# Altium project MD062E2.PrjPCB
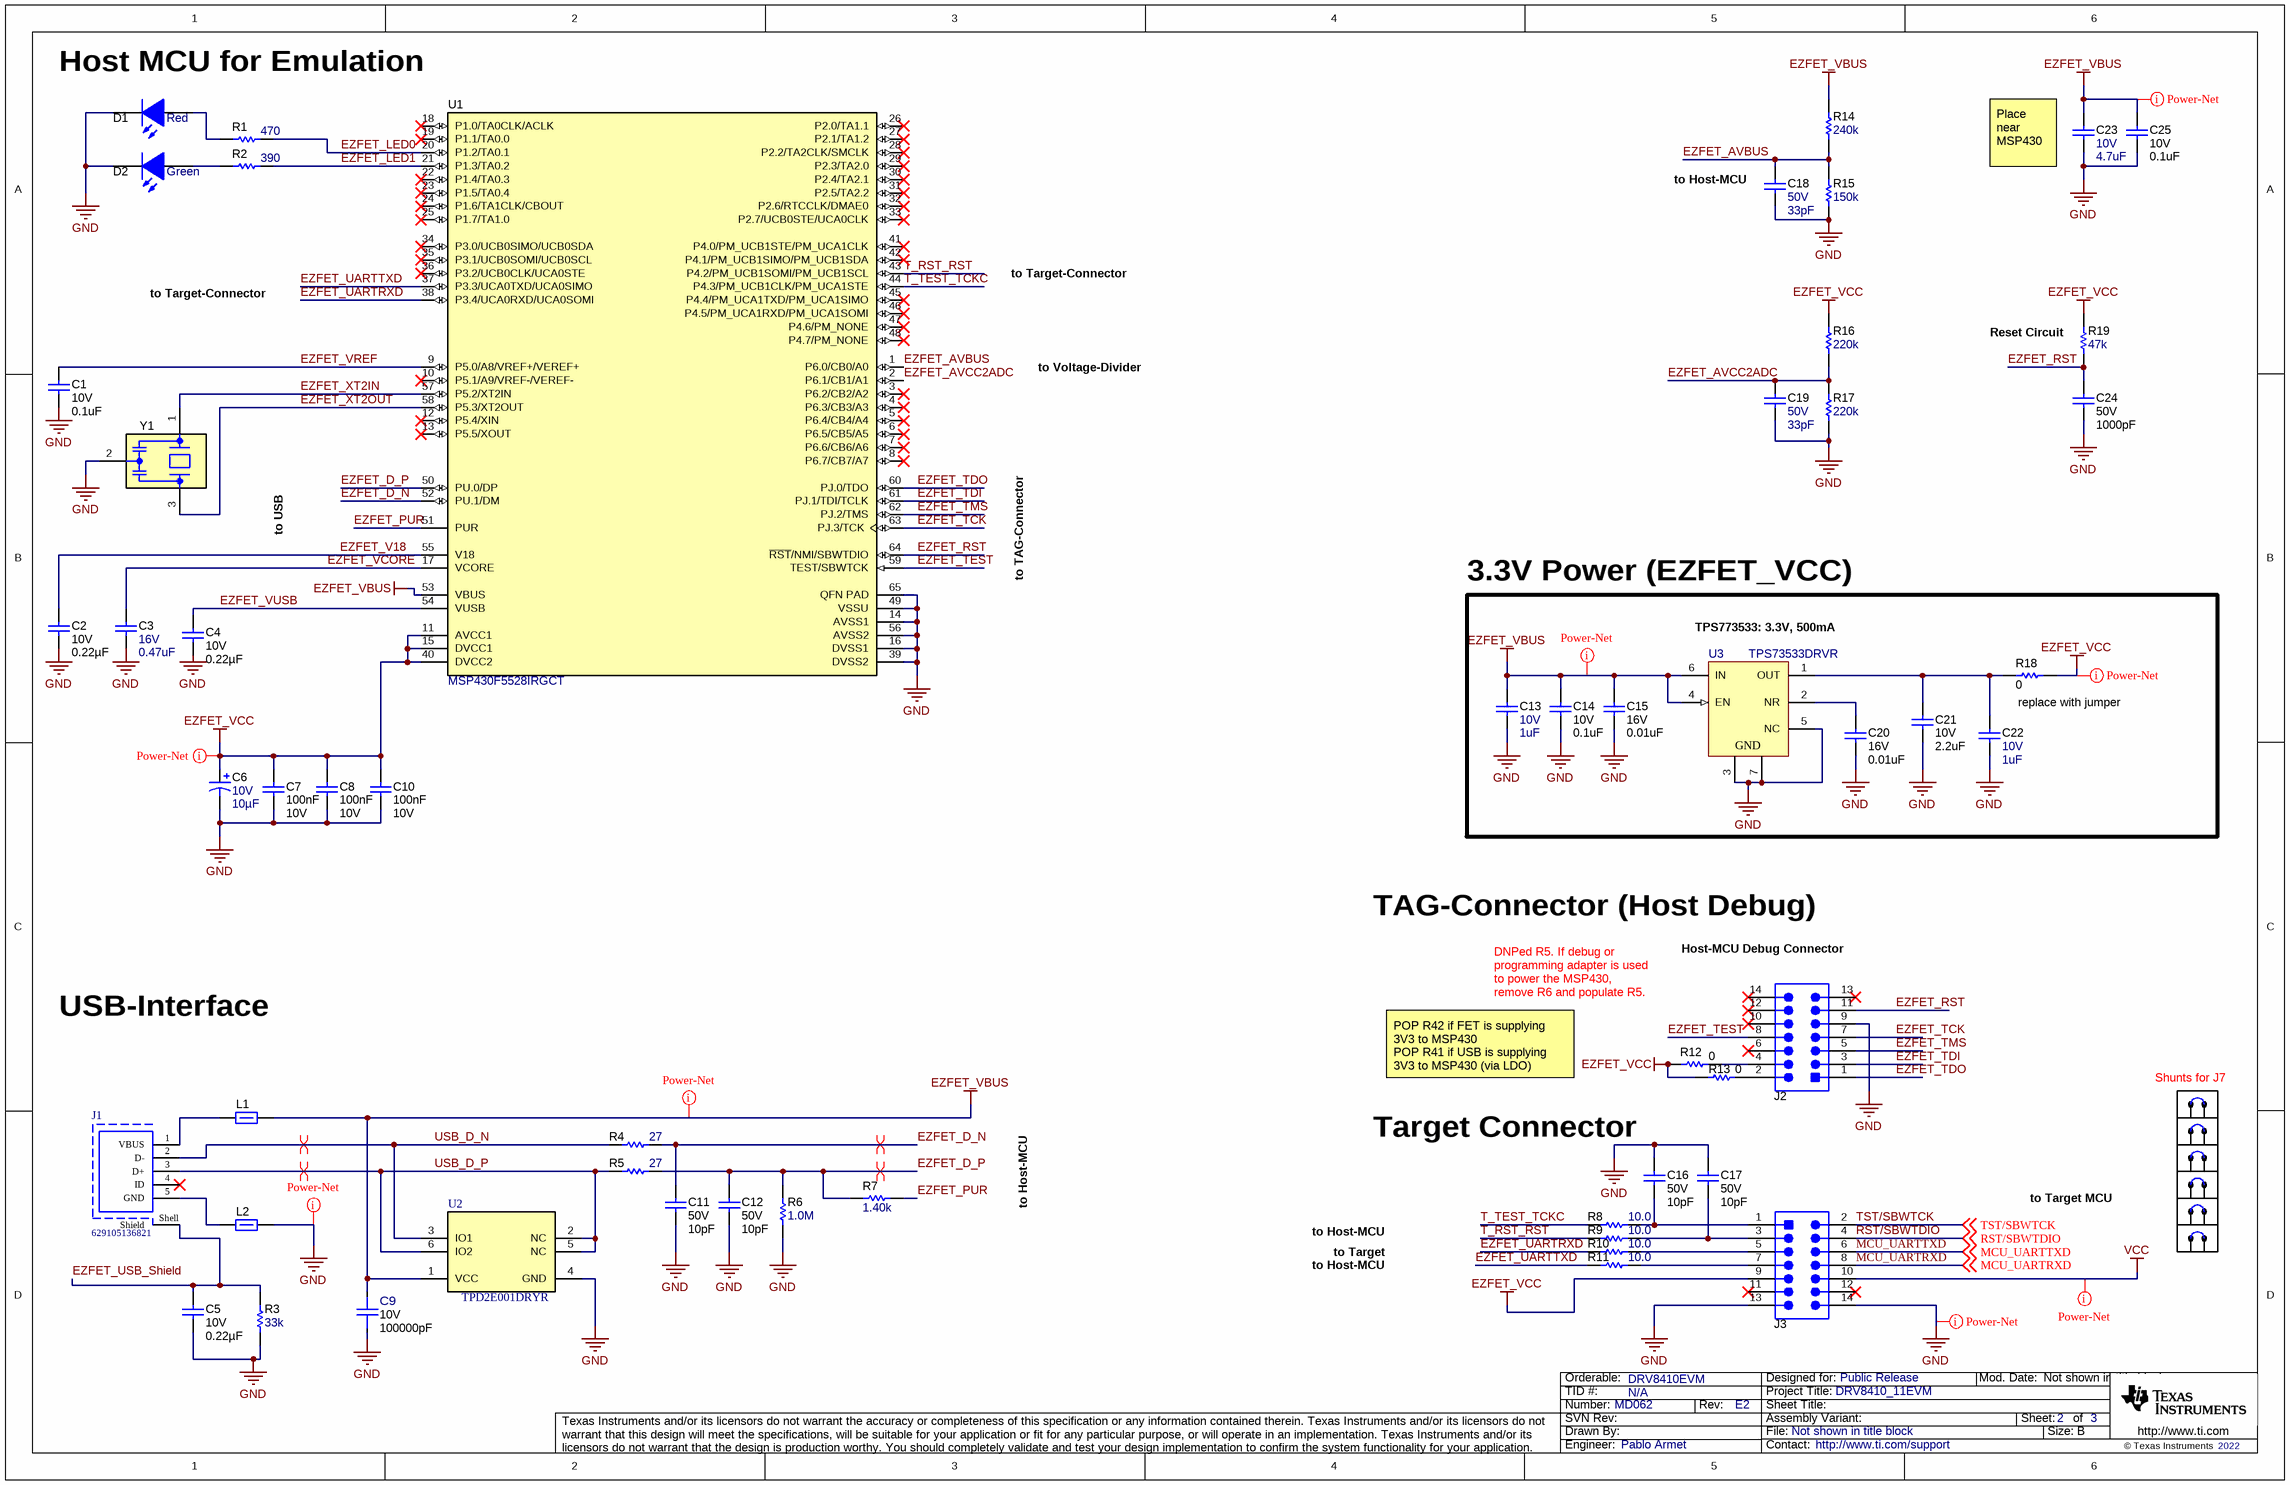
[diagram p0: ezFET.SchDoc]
CopyrightYear: 2022; EVM_Orderable: DRV8410EVM; PCB_Layout: Pablo Armet; PCB_Rev: E2; PRJ_Customer: Public Release; PRJ_Engineer: Pablo Armet; PRJ_Number: MD062; PRJ_Title: DRV8410_11EVM; SCH_Rev: E2; TechSupport: http://www.ti.com/support; TID: N/A
3 sheets, 173 parts. Net scope: global (net labels, ports and power ports of the same name join across sheets).
Board file: MD062E2_PCB.PcbDoc
Sheets:
  ezFET.SchDoc
  MD062E2_Hardware.SchDoc
  MD062E2_Sch.SchDoc

## Sheet ezFET.SchDoc
size 431 x 279 mm; Date: Not shown in title block; ApprovedBy: Not shown in title block; CheckedBy: Not shown in title block; Author: Not shown in title block; CompanyName: Not shown in title block; Engineer: Not shown in title block; Organization: Not shown in title block; Address1: Not shown in title block; Address2: Not shown in title block; Address3: Not shown in title block; Address4: Not shown in title block; DocumentNumber: 2; Revision: Use project parameter SCH_Rev; SheetNumber: 2; SheetTotal: 3; PageSetup: Record=PageOptions¦CenterHorizontal=True¦CenterVertical=True¦PrintScale=1.00¦XCorrection=1.00¦YCorrection=1.00¦PrintKind=0¦BorderSize=5000000¦LeftOffset=0¦BottomOffset=0¦Orientation=2¦PaperLength=1000¦PaperWidth=1000¦Scale=100¦PaperSource=15¦PrintQuality=600¦MediaType=1¦DitherType=10¦PaperKind=Letter¦PrintScaleMode=1

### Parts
C1  VDC_V: 10V  ValueDisplayed: 0.1uF  [0402L]  (hidden comment: 885012105010)
C2  VDC_V: 10V  ValueDisplayed: 0.22µF  [0402L]  (hidden comment: 885012105011)
C3  VDC_V: 16V  ValueDisplayed: 0.47uF  [0402L]  (hidden comment: GRM155R61C474KE01)
C4  VDC_V: 10V  ValueDisplayed: 0.22µF  [0402L]  (hidden comment: 885012105011)
C5  VDC_V: 10V  ValueDisplayed: 0.22µF  [0402S]  (hidden comment: 885012105011)
C6  VDC_V: 10V  ValueDisplayed: 10µF  [3216-18]  (hidden comment: T520A106M010ATE080)
C7  Cap_F: 100nF  VDC_V: 10V  [0603L]  (hidden comment: 885012206020)
C8  Cap_F: 100nF  VDC_V: 10V  [0603L]  (hidden comment: 885012206020)
C9  VDC_V: 10V  ValueDisplayed: 100000pF  [FP-885012205018_0402-MFG]  (hidden comment: 885012205018)
C10  Cap_F: 100nF  VDC_V: 10V  [0603L]  (hidden comment: 885012206020)
C11  VDC_V: 50V  ValueDisplayed: 10pF  [0402L]  (hidden comment: 885012005055)
C12  VDC_V: 50V  ValueDisplayed: 10pF  [0402L]  (hidden comment: 885012005055)
C13  VDC_V: 10V  ValueDisplayed: 1uF  [0402S]  (hidden comment: 885012105012)
C14  VDC_V: 10V  ValueDisplayed: 0.1uF  [0402S]  (hidden comment: 885012105010)
C15  VDC_V: 16V  ValueDisplayed: 0.01uF  [0402S]  (hidden comment: 885012205031)
C16  VDC_V: 50V  ValueDisplayed: 10pF  [0402L]  (hidden comment: 885012005055)
C17  VDC_V: 50V  ValueDisplayed: 10pF  [0402L]  (hidden comment: 885012005055)
C18  VDC_V: 50V  ValueDisplayed: 33pF  [0402L]  (hidden comment: C1005C0G1H330J050BA)
C19  VDC_V: 50V  ValueDisplayed: 33pF  [0402L]  (hidden comment: C1005C0G1H330J050BA)
C20  VDC_V: 16V  ValueDisplayed: 0.01uF  [0402S]  (hidden comment: 885012205031)
C21  VDC_V: 10V  ValueDisplayed: 2.2uF  [0402S]  (hidden comment: 885012105013)
C22  VDC_V: 10V  ValueDisplayed: 1uF  [0402S]  (hidden comment: 885012105012)
C23  VDC_V: 10V  ValueDisplayed: 4.7uF  [0402S]  (hidden comment: C1005X5R1A475M050BC)
C24  VDC_V: 50V  ValueDisplayed: 1000pF  [0402L]  (hidden comment: 885012205061)
C25  VDC_V: 10V  ValueDisplayed: 0.1uF  [0402S]  (hidden comment: GRM155R61A104KA01D)
D1  value Red  [WL-SMCW_RED]  (hidden comment: 150060RS75000)
D2  value Green  [WL-SMCW_GREEN]  (hidden comment: CMP-0002894-2)
J1  629105136821  [629105136821]
J2  61301421121  [Wurth_61301421121]  (value not drawn)
J3  61301421121  [Wurth_61301421121]  (value not drawn)
L1  742792621  [0603L]  (value not drawn)
L2  742792621  [0603L]  (value not drawn)
R1  ValueDisplayed: 470  [0402L]  (hidden comment: CRCW0402470RJNED)
R2  ValueDisplayed: 390  [0402L]  (hidden comment: CRCW0402390RJNED)
R3  ValueDisplayed: 33k  [0402S]  (hidden comment: CRCW040233K0JNED)
R4  ValueDisplayed: 27  [0402L]  (hidden comment: CRCW040227R0JNED)
R5  ValueDisplayed: 27  [0402L]  (hidden comment: CRCW040227R0JNED)
R6  ValueDisplayed: 1.0M  [0402L]  (hidden comment: CRCW04021M00JNED)
R7  ValueDisplayed: 1.40k  [0402L]  (hidden comment: CRCW04021K40FKED)
R8  ValueDisplayed: 10.0  [0402S]  (hidden comment: CRCW040210R0FKED)
R9  ValueDisplayed: 10.0  [0402S]  (hidden comment: CRCW040210R0FKED)
R10  ValueDisplayed: 10.0  [0402S]  (hidden comment: CRCW040210R0FKED)
R11  ValueDisplayed: 10.0  [0402S]  (hidden comment: CRCW040210R0FKED)
R12  value 0  [0402L]  (hidden comment: ERJ-2GE0R00X)
R13  value 0  [0402L]  (hidden comment: ERJ-2GE0R00X)
R14  ValueDisplayed: 240k  [0402L]  (hidden comment: CRCW0402240KFKED)
R15  ValueDisplayed: 150k  [0402L]  (hidden comment: CRCW0402150KFKED)
R16  ValueDisplayed: 220k  [0402L]  (hidden comment: RC0402FR-07220KL)
R17  ValueDisplayed: 220k  [0402L]  (hidden comment: RC0402FR-07220KL)
R18  ValueDisplayed: 0  [0402S]  (hidden comment: CRCW04020000Z0EDHP)
R19  ValueDisplayed: 47k  [0402L]  (hidden comment: CRCW040247K0JNED)
SH-J1  60900213421  [Wurth_60900213421]  (value not drawn)
SH-J2  60900213421  [Wurth_60900213421]  (value not drawn)
SH-J3  60900213421  [Wurth_60900213421]  (value not drawn)
SH-J4  60900213421  [Wurth_60900213421]  (value not drawn)
SH-J5  60900213421  [Wurth_60900213421]  (value not drawn)
SH-J6  60900213421  [Wurth_60900213421]  (value not drawn)
U1  PartNumber: MSP430F5528IRGCT  [RGC0064B]  (hidden comment: CMP-0039269-4)
U2  TPD2E001DRYR  [DRY0006A]
U3  TPS73533DRVR  [DRV0006A]
Y1  CSTNR4M00GH5L000R0  [MuRata_CSTNR]  (value not drawn)

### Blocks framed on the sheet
3.3V Power (EZFET_VCC): C13-C15 C20-C22 R18 U3

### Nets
EZFET_VBUS: C9.2 C13.1 C14.1 C15.1 C23.1 C25.1 L1.2 R14.2 U1.53(VBUS) U2.1(VCC) U3.4(EN) U3.6(IN)
EZFET_VCC: C6.1(+) C7.1 C8.1 C10.1 J3.9 R12.1 R13.1 R16.2 R18.2 R19.2 U1.11(AVCC1) U1.15(DVCC1) U1.40(DVCC2)
GND: C1.2 C2.2 C3.2 C4.2 C5.2 C6.2(-) C7.2 C8.2 C9.1 C10.2 C11.2 C12.2 C13.2 C14.2 C15.2 C16.1 C17.1 C18.2 C19.2 C20.2 C21.2 C22.2 C23.2 C24.2 C25.2 D1.1(K) D2.1(K) J2.9 J3.13 J3.14 L2.2 R3.1 R6.1 R15.1 R17.1 U1.14(AVSS1) U1.16(DVSS1) U1.39(DVSS2) U1.49(VSSU) U1.56(AVSS2) U1.65(QFN_PAD) U2.4(GND) U3.3(GND) U3.5(NC) U3.7(GND) Y1.2(GND)
VCC: J3.10
EZFET_AVBUS: C18.1 R14.1 R15.2 U1.1(P6.0/CB0/A0)
EZFET_AVCC2ADC: C19.1 R16.1 R17.2 U1.2(P6.1/CB1/A1)
EZFET_D_N: C11.1 R4.2 U1.52(PU.1/DM)
EZFET_D_P: C12.1 R5.2 R6.2 R7.1 U1.50(PU.0/DP)
EZFET_LED0: R1.2 U1.20(P1.2/TA0.1)
EZFET_LED1: R2.2 U1.21(P1.3/TA0.2)
EZFET_PUR: R7.2 U1.51(PUR)
EZFET_RST: C24.1 J2.11 R19.1 U1.64(~{RST}/NMI/SBWTDIO)
EZFET_TCK: J2.7 U1.63(PJ.3/TCK)
EZFET_TDI: J2.3 U1.61(PJ.1/TDI/TCLK)
EZFET_TDO: J2.1 U1.60(PJ.0/TDO)
EZFET_TEST: J2.8 U1.59(TEST/SBWTCK)
EZFET_TMS: J2.5 U1.62(PJ.2/TMS)
EZFET_UARTRXD: R10.1 U1.38(P3.4/UCA0RXD/UCA0SOMI)
EZFET_UARTTXD: R11.1 U1.37(P3.3/UCA0TXD/UCA0SIMO)
EZFET_USB_Shield: C5.1 J1.Shell(Shield) R3.2
EZFET_V18: C2.1 U1.55(V18)
EZFET_VCORE: C3.1 U1.17(VCORE)
EZFET_VREF: C1.1 U1.9(P5.0/A8/VREF+/VEREF+)
EZFET_VUSB: C4.1 U1.54(VUSB)
EZFET_XT2IN: U1.57(P5.2/XT2IN) Y1.1(In)
EZFET_XT2OUT: U1.58(P5.3/XT2OUT) Y1.3(Out)
MCU_UARTRXD: J3.8 ; off-sheet MCU_UARTRXD
MCU_UARTTXD: J3.6 ; off-sheet MCU_UARTTXD
RST/SBWTDIO: J3.4 ; off-sheet RST/SBWTDIO
T_RST_RST: R9.1 U1.43(P4.2/PM_UCB1SOMI/PM_UCB1SCL)
T_TEST_TCKC: R8.1 U1.44(P4.3/PM_UCB1CLK/PM_UCA1STE)
TST/SBWTCK: J3.2 ; off-sheet TST/SBWTCK
USB_D_N: J1.2(D-) R4.1 U2.3(IO1)
USB_D_P: J1.3(D+) R5.1 U2.2(NC) U2.5(NC) U2.6(IO2)
NetC16_2: C16.2 J3.1 R8.2
NetC17_2: C17.2 J3.3 R9.2
NetC20_1: C20.1 U3.2(NR)
NetC21_1: C21.1 C22.1 R18.1 U3.1(OUT)
NetD1_2: D1.2(A) R1.1
NetD2_2: D2.2(A) R2.1
NetJ1_1: J1.1(VBUS) L1.1
NetJ1_5: J1.5(GND) L2.1
NetJ2_2: J2.2 R13.2
NetJ2_4: J2.4 R12.2
NetJ3_5: J3.5 R10.2
NetJ3_7: J3.7 R11.2

Not connected (* = marked no-connect by the designer): J1 4(ID)*; J2 6* 10* 12* 13* 14*; J3 11* 12*; U1 3(P6.2/CB2/A2)* 4(P6.3/CB3/A3)* 5(P6.4/CB4/A4)* 6(P6.5/CB5/A5)* 7(P6.6/CB6/A6)* 8(P6.7/CB7/A7)* 10(P5.1/A9/VREF-/VEREF-)* 12(P5.4/XIN)* 13(P5.5/XOUT)* 18(P1.0/TA0CLK/ACLK)* 19(P1.1/TA0.0)* 22(P1.4/TA0.3)* 23(P1.5/TA0.4)* 24(P1.6/TA1CLK/CBOUT)* 25(P1.7/TA1.0)* 26(P2.0/TA1.1)* 27(P2.1/TA1.2)* 28(P2.2/TA2CLK/SMCLK)* 29(P2.3/TA2.0)* 30(P2.4/TA2.1)* 31(P2.5/TA2.2)* 32(P2.6/RTCCLK/DMAE0)* 33(P2.7/UCB0STE/UCA0CLK)* 34(P3.0/UCB0SIMO/UCB0SDA)* 35(P3.1/UCB0SOMI/UCB0SCL)* 36(P3.2/UCB0CLK/UCA0STE)* 41(P4.0/PM_UCB1STE/PM_UCA1CLK)* 42(P4.1/PM_UCB1SIMO/PM_UCB1SDA)* 45(P4.4/PM_UCA1TXD/PM_UCA1SIMO)* 46(P4.5/PM_UCA1RXD/PM_UCA1SOMI)* 47(P4.6/PM_NONE)* 48(P4.7/PM_NONE)*

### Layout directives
net class Power-Net: EZFET_VBUS, EZFET_VCC, GND, VCC
differential pair: EZFET_D_N, EZFET_D_P, USB_D_N, USB_D_P

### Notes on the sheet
- (near D1) Host MCU for Emulation
- (near C23) Place near MSP430
- (near C18) to Host-MCU
- to Target-Connector
- to Voltage-Divider
- (near R19) Reset Circuit
- to USB
- to TAG-Connector
- (near U3) TPS773533: 3.3V, 500mA
- replace with jumper
- TAG-Connector (Host Debug)
- (near J2) Host-MCU Debug Connector
- USB-Interface
- DNPed R5. If debug or programming adapter is used to power the MSP430, remove R6 and populate R5.
- POP R42 if FET is supplying 3V3 to MSP430
  POP R41 if USB is supplying 3V3 to MSP430 (via LDO)
- (near SH-J1) Shunts for J7
- to Host-MCU
- Target Connector
- to Target MCU
- to Target

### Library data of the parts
C1 C14 = CMP-0006221-2: CAP, CERM, 0.1 uF, 10 V, +/- 20%, X5R, 0402; Manufacturer: Wurth Elektronik; TaMin_C: -55°C; Polarized: N; SizeAreaWB_mm2: 3; Value1: Unknown; U/M: EA; Value: 0.1uF; TaMax_C: 85°C; SizeZ_mm: 0.6; SizeX_mm: 1; SizeY_mm: 0.5; Cap_Case: 0402; Cap_F: 100nF; AEC Category: Q200
C2 C4 C5 = CMP-0078875-1: CAP, CERM, 0.22 µF, 10 V,+/- 20%, X5R, 0402; Manufacturer: Wurth Elektronik; TaMin_C: -55°C; Polarized: N; SizeAreaWB_mm2: 3; U/M: EA; Value: 0.22uF; TaMax_C: 85°C; SizeZ_mm: 0.6; SizeX_mm: 1; SizeY_mm: 0.5; Cap_Case: 0402; Cap_F: 220nF; AEC Category: Q200
C3 = CMP-0006600-2: CAP, CERM, 0.47 uF, 16 V, +/- 10%, X5R, 0402; Manufacturer: MuRata; TaMin_C: -55°C; Polarized: N; SizeAreaWB_mm2: 3; Value1: Unknown; U/M: EA; Value: 0.47uF; TaMax_C: 85°C; SizeZ_mm: 0.6; SizeX_mm: 1; SizeY_mm: 0.5; Cap_Case: 0402; Cap_F: 470nF; AEC Category: Q200
C6 = CMP-0084376-1: CAP, Tantalum Polymer, 10 µF, 10 V,+/- 20%, 0.08 ohm, 3216-18 SMD; Manufacturer: Kemet; TaMin_C: -55°C; SizeArea_mm2: 5.12; Value: 10uF; SizeAreaWB_mm2: 10.92; SizeY_mm: 1.6; Polarized: Y; SizeX_mm: 3.2; AEC Qualified: N; TaMax_C: 105°C; SizeZ_mm: 1.8; ESR_ohm: 0.08; CompType: Capacitor; AEC Category: Q200
C7 C8 C10 = CMP-0064931-4: CAP, CERM, 0.1 uF, 10 V,+/- 10%, X7R, 0603; Manufacturer: Wurth Elektronik; TaMin_C: -55°C; Polarized: N; SizeAreaWB_mm2: 4.68; Value1: Unknown; U/M: EA; Value: 0.1uF; TaMax_C: 125°C; SizeZ_mm: 1; SizeX_mm: 1.6; SizeY_mm: 0.8; Cap_Case: 0603; SizeArea_mm2: 1.28; AEC Category: Q200
C9 = CMP-0090362-1: 0.1µF ±10% 10V Ceramic Capacitor X7R 0402 (1005 Metric); Manufacturer: Wurth Electronics; AEC Qualified: No; Value: 100nF; SizeZ_mm: 0.55mm; TempCo: 15%
C11 C12 C16 C17 = CMP-0006215-2: CAP, CERM, 10 pF, 50 V, +/- 5%, C0G/NP0, 0402; Manufacturer: Wurth Elektronik; TaMin_C: -55°C; Polarized: N; SizeAreaWB_mm2: 3; Value1: Unknown; U/M: EA; Value: 10pF; TaMax_C: 125°C; SizeZ_mm: 0.6; SizeX_mm: 1; SizeY_mm: 0.5; Cap_Case: 0402; AEC Category: Q200
C13 C22 = CMP-0064924-2: CAP, CERM, 1 uF, 10 V,+/- 20%, X5R, 0402; Manufacturer: Wurth Elektronik; TaMin_C: -55°C; Polarized: N; SizeAreaWB_mm2: 3; Value1: Unknown; U/M: EA; Value: 1uF; TaMax_C: 85°C; SizeZ_mm: 0.6; SizeX_mm: 1; SizeY_mm: 0.5; Cap_Case: 0402; Cap_F: 1µF; AEC Category: Q200
C15 C20 = CMP-0006227-2: CAP, CERM, 0.01 uF, 16 V, +/- 10%, X7R, 0402; Manufacturer: Wurth Elektronik; TaMin_C: -55°C; Polarized: N; SizeAreaWB_mm2: 3; Value1: Unknown; U/M: EA; Value: 0.01uF; TaMax_C: 125°C; SizeZ_mm: 0.6; SizeX_mm: 1; SizeY_mm: 0.5; Cap_Case: 0402; Cap_F: 10nF; AEC Category: Q200
C18 C19 = CMP-0006250-2: CAP, CERM, 33 pF, 50 V, +/- 5%, C0G/NP0, 0402; Manufacturer: TDK; TaMin_C: -55°C; Polarized: N; SizeAreaWB_mm2: 3; Value1: Unknown; U/M: EA; Value: 33pF; TaMax_C: 125°C; SizeZ_mm: 0.6; SizeX_mm: 1; SizeY_mm: 0.5; Cap_Case: 0402; AEC Category: Q200
C21 = CMP-0006222-2: CAP, CERM, 2.2 uF, 10 V, +/- 20%, X5R, 0402; Manufacturer: Wurth Elektronik; TaMin_C: -55°C; Polarized: N; SizeAreaWB_mm2: 3; Value1: Unknown; U/M: EA; Value: 2.2uF; TaMax_C: 85°C; SizeZ_mm: 0.6; SizeX_mm: 1; SizeY_mm: 0.5; Cap_Case: 0402; Cap_F: 2.2µF; AEC Category: Q200
C23 = CMP-0006269-2: CAP, CERM, 4.7 uF, 10 V, +/- 20%, X5R, 0402; Manufacturer: TDK; TaMin_C: -55°C; Polarized: N; SizeAreaWB_mm2: 3; Value1: Unknown; U/M: EA; Value: 4.7uF; TaMax_C: 85°C; SizeZ_mm: 0.6; SizeX_mm: 1; SizeY_mm: 0.5; Cap_Case: 0402; Cap_F: 4.7µF; AEC Category: Q200
C24 = CMP-0006231-2: CAP, CERM, 1000 pF, 50 V, +/- 10%, X7R, 0402; Manufacturer: Wurth Elektronik; TaMin_C: -55°C; Polarized: N; SizeAreaWB_mm2: 3; Value1: Unknown; U/M: EA; Value: 1000pF; TaMax_C: 125°C; SizeZ_mm: 0.6; SizeX_mm: 1; SizeY_mm: 0.5; Cap_Case: 0402; Cap_F: 1nF; AEC Category: Q200
C25 = CMP-0006562-2: CAP, CERM, 0.1 uF, 10 V, +/- 10%, X5R, 0402; Manufacturer: MuRata; TaMin_C: -55°C; Polarized: N; SizeAreaWB_mm2: 3; Value1: Unknown; U/M: EA; Value: 0.1uF; TaMax_C: 85°C; SizeZ_mm: 0.6; SizeX_mm: 1; SizeY_mm: 0.5; Cap_Case: 0402; Cap_F: 100nF; AEC Category: Q200
D1 = CMP-0002947-3: LED, Red, SMD; Manufacturer: Wurth Elektronik; Type: AlInGaP; Vf_V: 2V; Io_A: 30mA; Vr_V: 5V; Tjmax_C: 85°C; Power_TotalModule: 72mW; Value1: 0.072W; Angle: 140
D2 = CMP-0002894-2: LED, Green, SMD; Manufacturer: Wurth Elektronik; PartNumber: 150060VS75000; Type: AlInGaP; Vf_V: 2V; Io_A: 20mA; Value1: W
J1 = CMP-1502-03253-1: Micro USB 2.0 Type B Receptacle WR-COM, Horizontal, SMT, with Pads and Pegs; Manufacturer: Wurth Elektronik; Contact Resistance: 30mOhm; Rated Current: 1A; Working Voltage: 30VAC
J2 J3 = CMP-0086014-1: Header, 2.54mm, 7x2, Gold, TH; Manufacturer: Wurth Elektronik; Pitch_mm: 2.54; Voltage_V: 250V; Shrouded: N; Gender: Male; Current_A: 3A; Cert_UL: Y; Row_Count: 2
L1 L2 = CMP-0003184-2: Ferrite Bead, 140 ohm @ 100 MHz, 0.55 A, 0603; Manufacturer: Wurth Elektronik; Ztyp@1GHz_Ohm: 271.401; ZTyp@100MHz_Ohm: 140; SizeAreaWB_mm2: 4.68; DCR_ohm: 0.2; Value1: 0.2 ohm; Value: 140 ohm; Imax_A: 550mA; SizeZ_mm: 1; SizeX_mm: 1.6; SizeY_mm: 0.8; Value2: 0.55A; SizeArea_mm2: 1.28
R1 = CMP-0026934-3: RES, 470, 5%, 0.063 W, AEC-Q200 Grade 0, 0402; Manufacturer: Vishay-Dale; Value: 470; Value_Code: 470R; Power_W: 63mW; Value2: 0.063W; VDC_V: 50V; TempCo: 200 ppm/C; SizeArea_mm2: 0.5; SizeX_mm: 1; SizeZ_mm: 0.6; EIA_Code: E24; AEC Category: Q200; AEC Qualified: Y; AEC Grade: 0
R2 = CMP-0026914-3: RES, 390, 5%, 0.063 W, AEC-Q200 Grade 0, 0402; Manufacturer: Vishay-Dale; Value: 390; Value_Code: 390R; Power_W: 63mW; Value2: 0.063W; VDC_V: 50V; TempCo: 200 ppm/C; SizeArea_mm2: 0.5; SizeX_mm: 1; SizeZ_mm: 0.6; EIA_Code: E24; AEC Category: Q200; AEC Qualified: Y; AEC Grade: 0
R3 = CMP-0026907-3: RES, 33 k, 5%, 0.063 W, AEC-Q200 Grade 0, 0402; Manufacturer: Vishay-Dale; Power_W: 63mW; TempCo: 200 ppm/C; Value_Code: 33k0; Value: 33k; EIA_Code: E24; SizeX_mm: 1; SizeY_mm: 0.5; SizeZ_mm: 0.6; Value2: 0.063W; AEC Qualified: Y; VDC_V: 50V; AEC Category: Q200; AEC Grade: 0
R4 R5 = CMP-0026888-3: RES, 27, 5%, 0.063 W, AEC-Q200 Grade 0, 0402; Manufacturer: Vishay-Dale; Power_W: 63mW; TempCo: 200 ppm/C; Value_Code: 27R0; Value: 27; EIA_Code: E24; SizeX_mm: 1; SizeY_mm: 0.5; SizeZ_mm: 0.6; Value2: 0.063W; AEC Qualified: Y; VDC_V: 50V; AEC Category: Q200; AEC Grade: 0
R6 = CMP-0026859-2: RES, 1.0 M, 5%, 0.063 W, AEC-Q200 Grade 0, 0402; Manufacturer: Vishay-Dale; Power_W: 63mW; TempCo: 200 ppm/C; Value_Code: 1M00; Value: 1.0Meg; EIA_Code: E24; Res_ohm: 1M; SizeX_mm: 1; SizeY_mm: 0.5; SizeZ_mm: 0.6; Value2: 0.063W; AEC Qualified: Y; VDC_V: 50V; AEC Category: Q200; AEC Grade: 0
R7 = CMP-0026085-3: RES, 1.40 k, 1%, 0.063 W, AEC-Q200 Grade 0, 0402; Manufacturer: Vishay-Dale; Power_W: 63mW; TempCo: 100 ppm/C; Value_Code: 1k40; Value: 1.40k; EIA_Code: E96; Res_ohm: 1.4k; SizeX_mm: 1; SizeY_mm: 0.5; SizeZ_mm: 0.6; Value2: 0.063W; AEC Qualified: Y; VDC_V: 50V; AEC Category: Q200; AEC Grade: 0
R8-R11 = CMP-0025963-2: RES, 10.0, 1%, 0.063 W, 0402; Manufacturer: Vishay-Dale; Power_W: 63mW; TempCo: 100 ppm/C; Value_Code: 10R0; U/M: EA; Value: 10.0; EIA_Code: E96; Res_ohm: 10; SizeX_mm: 1; SizeY_mm: 0.5; SizeZ_mm: 0.6; Value2: 0.063W; VDC_V: 50V; AEC Category: Q200
R12 R13 = CMP-0026992-3: RES, 0, 5%, 0.1 W, AEC-Q200 Grade 0, 0402; Manufacturer: Panasonic; Value_Code: 0000; Power_W: 100mW; Value2: 0.1W; VDC_V: 50V; TempCo: 600 ppm/C; EIA_Code: E24; AEC Category: Q200; AEC Qualified: Y; SizeArea_mm2: 0.5; SizeAreaWB_mm2: 3; SizeX_mm: 1; SizeZ_mm: 0.6
R14 = CMP-0026190-2: RES, 240 k, 1%, 0.063 W, AEC-Q200 Grade 0, 0402; Manufacturer: Vishay-Dale; Power_W: 63mW; TempCo: 100 ppm/C; Value: 240k; SizeX_mm: 1; SizeY_mm: 0.5; SizeZ_mm: 0.6; Value2: 0.063W; AEC Qualified: Y; VDC_V: 50V; AEC Category: Q200; AEC Grade: 0
R15 = CMP-0026021-3: RES, 150 k, 1%, 0.063 W, AEC-Q200 Grade 0, 0402; Manufacturer: Vishay-Dale; Power_W: 63mW; TempCo: 100 ppm/C; Value: 150k; EIA_Code: E96; SizeX_mm: 1; SizeY_mm: 0.5; SizeZ_mm: 0.6; Value2: 0.063W; AEC Qualified: Y; VDC_V: 50V; AEC Category: Q200; AEC Grade: 0
R16 R17 = CMP-0026728-1: RES, 220 k, 1%, 0.0625 W, 0402; Manufacturer: Yageo America; Power_W: 62.5mW; TempCo: 100 ppm/C; U/M: EA; Value: 220k; SizeX_mm: 1; SizeY_mm: 0.5; SizeZ_mm: 0.6; AEC Qualified: N; VDC_V: 50V; AEC Category: Q200
R18 = CMP-0081856-1: RES, 0, 0%, 0.2 W, AEC-Q200 Grade 0, 0402; Manufacturer: Vishay-Dale; SizeAreaWB_mm2: 3; SizeArea_mm2: 0.5; AEC Qualified: Y; AEC Category: Q200; Value: 0; SizeZ_mm: 0.6; Power_W: 200mW; VDC_V: 50V; Value2: 0.2W; SizeX_mm: 1
R19 = CMP-0026935-3: RES, 47 k, 5%, 0.063 W, AEC-Q200 Grade 0, 0402; Manufacturer: Vishay-Dale; Power_W: 63mW; TempCo: 200 ppm/C; Value_Code: 47k0; Value: 47k; EIA_Code: E24; SizeX_mm: 1; SizeY_mm: 0.5; SizeZ_mm: 0.6; Value2: 0.063W; AEC Qualified: Y; VDC_V: 50V; AEC Category: Q200; AEC Grade: 0
SH-J1-SH-J6 = CMP-0003761-2: Shunt, 2.54mm, Gold, Black; Manufacturer: Wurth Elektronik
U1 = CMP-0039269-4: 16-Bit Ultra-Low-Power Microcontroller, 128KB Flash, 8KB RAM, USB, 12Bit ADC, 2 USCIs, 32Bit HW MPY, RGC0064B (VQFN-64); Alternate Manufacturer: Texas Instruments; Alternate PartNumber: MSP430F5528IRGCR; ADC: 12-bit SAR; ADC Channels: 16; Brown Out Reset: Yes; DMA: 3; Flash(KB): 128; Frequency(MHz): 25; GPIO: 47; Multiplier: 32x32; SRAM(B): 8192; Timers - 16-bit: 4; USB: 1; USCI_A (UART/LIN/IrDA/SPI): 2; Rating: Catalog; SizeArea_mm2: 81.0; SizeZ_mm: 1.0; Green_REACh: Passed; AEC Qualified: N; AEC Category: Q200; CompType: IC; Green_Lifecycle: Active; SizeY_mm: 9.0; SizeAreaWB_mm2: 121.0
U2 = CMP-0043099-3: Low-Capacitance 2-Channel +/-15kV ESD Protection Array for High-Speed Data Interfaces, DRY0006A (USON-6); Manufacturer: Texas Instruments; PartNumber: q; IO Leakage Current(nA): 1; IEC 61000-4-2 Air-Gap(+/- kV): 15; USB High Speed: TRUE; IO Capacitance(Typ)(pF): 1.5; Eco-Plan: Green (RoHS & no Sb/Br); Breakdown Voltage(Min)(V): 11; IEC 61000-4-2 Contact(+/- kV): 8; AEC Category: Q200; AEC Qualified: N; CompType: IC; SizeAreaWB_mm2: 4.9; SizeArea_mm2: 1.45; SizeX_mm: 1.0; SizeZ_mm: 0.6; Rating: Catalog
U3 = CMP-0036330-5: Single Output High PSRR LDO, 500 mA, Fixed 3.3 V Output, 2.7 to 6.5 V Input, with Low IQ, 6-pin SON (DRV), -40 to 125 degC, Green (RoHS & no Sb/Br); Manufacturer: Texas Instruments; SubFamily: Single Channel LDO; Vin(Max)(V): 6.5; Vin(Min)(V): 2.7; Iout(Max)(A): 0.5; Iq(Typ)(mA): 0.04; Fixed Output Options(V): 3.3; Vdo(Typ)(mV): 280; Accuracy(%): 2; CompType: IC; SizeAreaWB_mm2: 9; SizeArea_mm2: 4; SizeZ_mm: 0.8
Y1 = CMP-0085483-1: Oscillator, 4 MHz, 700 ppm, 39 pF, SMD; Manufacturer: MuRata; SizeArea_mm2: 9; Load Capacitance: 39 pF; SizeZ_mm: 1.2; AEC Category: Q200; Frequency Tolerance: 700 ppm; SizeX_mm: 4.5; SizeAreaWB_mm2: 16.5; TaMax_C: 85°C; TaMin_C: -20°C; SizeY_mm: 2; AEC Qualified: N; Frequency_Fixed: 4MHz

## Sheet MD062E2_Hardware.SchDoc
size 431 x 279 mm; Date: Not shown in title block; ApprovedBy: Not shown in title block; CheckedBy: Not shown in title block; Author: Not shown in title block; CompanyName: Not shown in title block; Engineer: Not shown in title block; Organization: Not shown in title block; Address1: Not shown in title block; Address2: Not shown in title block; Address3: Not shown in title block; Address4: Not shown in title block; DocumentNumber: 3; Revision: Use project parameter SCH_Rev; SheetNumber: 3; SheetTotal: 3; PageSetup: Record=PageOptions¦CenterHorizontal=True¦CenterVertical=True¦PrintScale=1.00¦XCorrection=1.00¦YCorrection=1.00¦PrintKind=0¦BorderSize=5000000¦LeftOffset=0¦BottomOffset=0¦Orientation=2¦PaperLength=1000¦PaperWidth=1000¦Scale=100¦PaperSource=15¦PrintQuality=600¦MediaType=1¦DitherType=10¦PaperKind=Letter¦PrintScaleMode=1
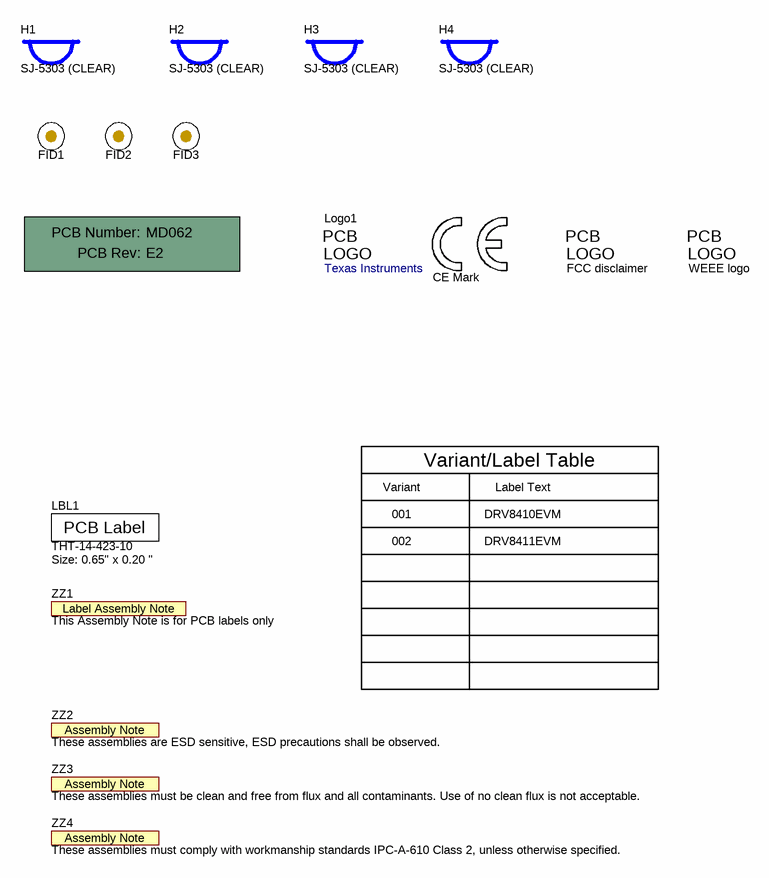
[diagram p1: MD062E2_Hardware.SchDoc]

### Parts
!PCB1  Printed Circuit Board  (value not drawn)  (mechanical)
FID1  Fiducial  [Fiducial10-20]  (value not drawn)
FID2  Fiducial  [Fiducial10-20]  (value not drawn)
FID3  Fiducial  [Fiducial10-20]  (value not drawn)
H1  SJ-5303 (CLEAR)  [Bumpon_SJ5003Transparent]
H2  SJ-5303 (CLEAR)  [Bumpon_SJ5003Transparent]
H3  SJ-5303 (CLEAR)  [Bumpon_SJ5003Transparent]
H4  SJ-5303 (CLEAR)  [Bumpon_SJ5003Transparent]
LBL1  THT-14-423-10  Note: Size: 0.65" x 0.20 "  [Label_650x200]
Logo1  Texas Instruments  [TI_Symbol_Overlay_Medium]  (no BOM)
Logo2  CE Mark  [CE_Mark_5mm]  (no BOM)
Logo3  FCC disclaimer  [FCC_disclaimer]  (no BOM)
Logo4  WEEE logo  [WEEE_Minimum]  (no BOM)
ZZ1  This Assembly Note is for PCB labels only  [AssemblyNoteLabel]  (no BOM)
ZZ2  These assemblies are ESD sensitive, ESD precautions shall be observed.  [AssemblyNote]  (no BOM)
ZZ3  These assemblies must be clean and free from flux and all contaminants. Use of no clean flux is not acceptable.  [AssemblyNote]  (no BOM)
ZZ4  These assemblies must comply with workmanship standards IPC-A-610 Class 2, unless otherwise specified.  [AssemblyNote]  (no BOM)

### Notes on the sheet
- Variant
- Variant/Label Table
- Label Text
- 001
- 002
- DRV8410EVM
- DRV8411EVM

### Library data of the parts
!PCB1 = CMP-0003618-2: Manufacturer: Any; PartNumber: MD062
FID1-FID3 = CMP-0077181-1: Fiducial mark.  There is nothing to buy or mount.
H1-H4 = CMP-0003620-1: Bumpon, Hemisphere, 0.44 X 0.20, Clear; Manufacturer: 3M
LBL1 = CMP-0003625-1: Thermal Transfer Printable Labels, 0.650" W x 0.200" H - 10,000 per roll; Manufacturer: Brady; CompType: Label
Logo1 = CMP-0074838-1: Texas Instrument Corporate Signature; SymbolCreator: a0412235; Lib Reference: TI_Logo
Logo2 = CMP-0074844-1: SymbolCreator: a0412235
Logo3 = CMP-0074847-1: FCC_disclaimer; Library Reference: Logo
Logo4 = CMP-0074769-1
ZZ1 = CMP-0003616-3
ZZ2 = CMP-0077236-1
ZZ3 = CMP-0077237-1
ZZ4 = CMP-0077238-1

## Sheet MD062E2_Sch.SchDoc
size 431 x 279 mm; Date: Not shown in title block; ApprovedBy: Not shown in title block; CheckedBy: Not shown in title block; Author: Not shown in title block; CompanyName: Not shown in title block; Engineer: Not shown in title block; Organization: Not shown in title block; Address1: Not shown in title block; Address2: Not shown in title block; Address3: Not shown in title block; Address4: Not shown in title block; DocumentNumber: 2; Revision: Use project parameter SCH_Rev; SheetNumber: 2; SheetTotal: 3; PageSetup: Record=PageOptions¦CenterHorizontal=True¦CenterVertical=True¦PrintScale=1.00¦XCorrection=1.00¦YCorrection=1.00¦PrintKind=0¦BorderSize=5000000¦LeftOffset=0¦BottomOffset=0¦Orientation=2¦PaperLength=1000¦PaperWidth=1000¦Scale=100¦PaperSource=15¦PrintQuality=600¦MediaType=1¦DitherType=10¦PaperKind=Letter¦PrintScaleMode=1
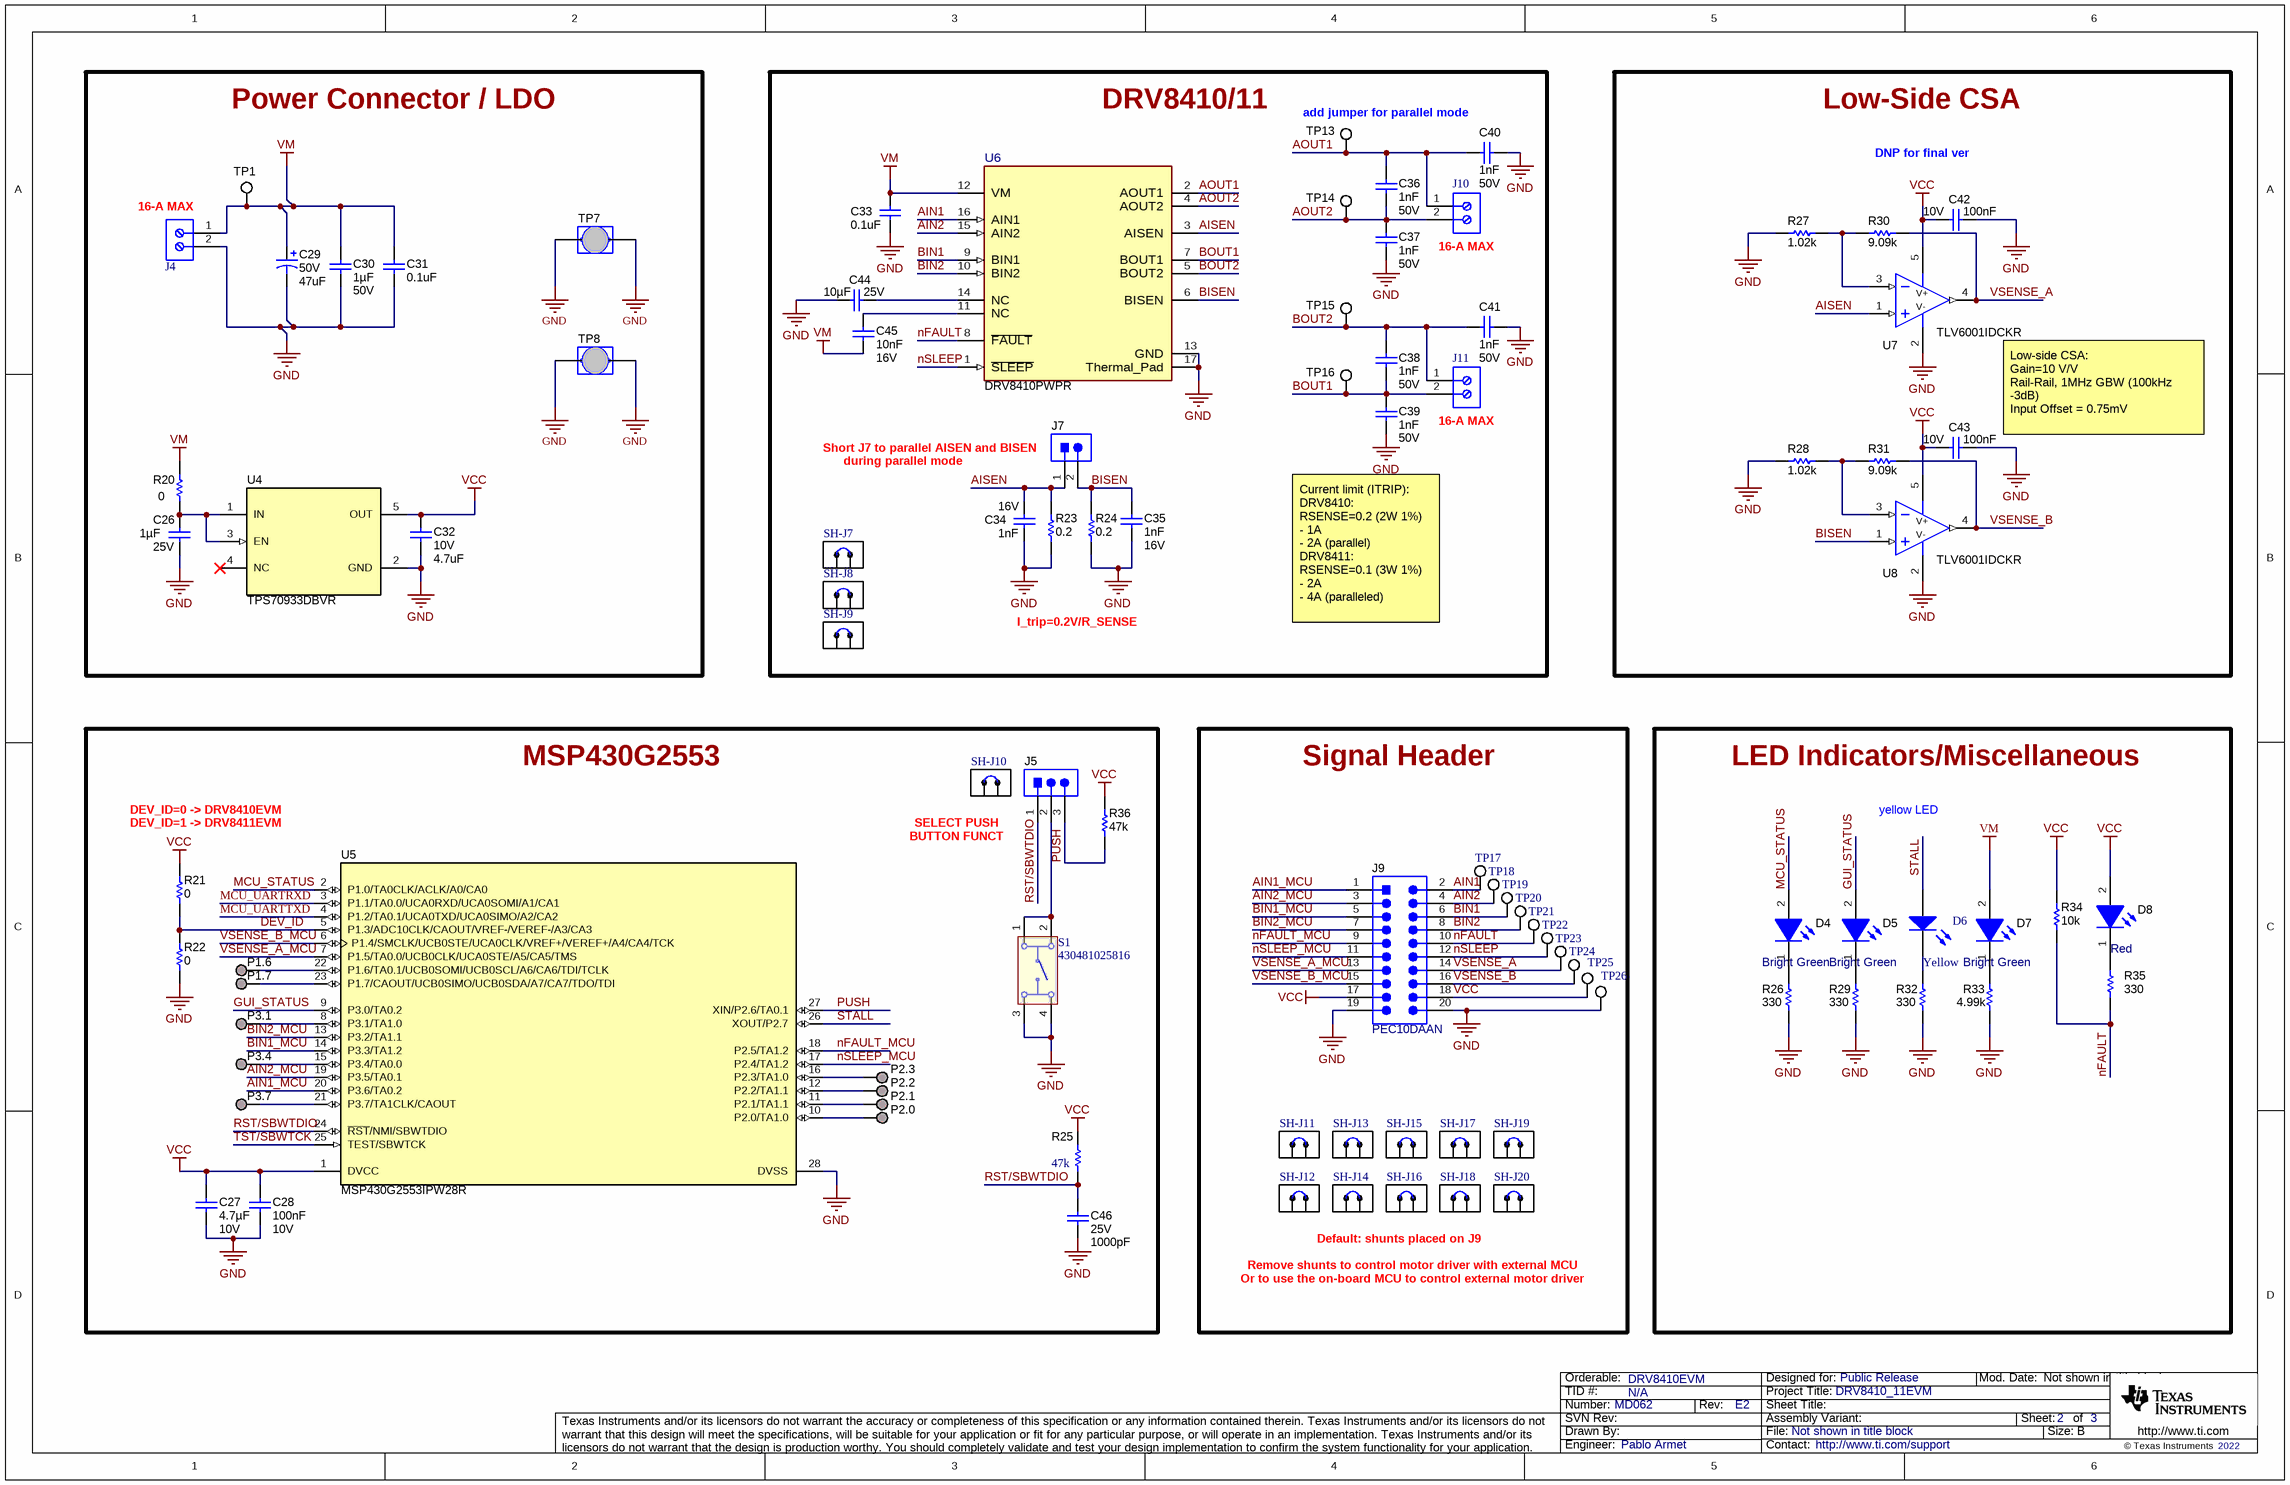
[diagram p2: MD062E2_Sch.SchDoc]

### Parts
C26  Cap_F: 1µF  VDC_V: 25V  [0603S]  (hidden comment: 885012206076)
C27  Cap_F: 4.7µF  VDC_V: 10V  [0805L]  (hidden comment: 885012207025)
C28  Cap_F: 100nF  VDC_V: 10V  [0603L]  (hidden comment: 885012206020)
C29  VDC_V: 50V  ValueDisplayed: 47uF  [WCAP-ASLI_630x770]  (hidden comment: 865080645012)
C30  Cap_F: 1µF  VDC_V: 50V  [0805L]  (hidden comment: 885012207103)
C31  ValueDisplayed: 0.1uF  [0603L]  (hidden comment: 885012206095)
C32  VDC_V: 10V  ValueDisplayed: 4.7uF  [0603S]  (hidden comment: GRM188R61A475ME15)
C33  ValueDisplayed: 0.1uF  [0603S]  (hidden comment: 885012206095)
C34  Cap_F: 1nF  VDC_V: 16V  [0603L]  (hidden comment: 885012206034)
C35  Cap_F: 1nF  VDC_V: 16V  [0603L]  (hidden comment: 885012206034)
C36  Cap_F: 1nF  VDC_V: 50V  [0603L]  (hidden comment: 885012206083)
C37  Cap_F: 1nF  VDC_V: 50V  [0603L]  (hidden comment: 885012206083)
C38  Cap_F: 1nF  VDC_V: 50V  [0603L]  (hidden comment: 885012206083)
C39  Cap_F: 1nF  VDC_V: 50V  [0603L]  (hidden comment: 885012206083)
C40  Cap_F: 1nF  VDC_V: 50V  [0603L]  (hidden comment: 885012206083)
C41  Cap_F: 1nF  VDC_V: 50V  [0603L]  (hidden comment: 885012206083)
C42  Cap_F: 100nF  VDC_V: 10V  [0603L]  (hidden comment: 885012206020)
C43  Cap_F: 100nF  VDC_V: 10V  [0603L]  (hidden comment: 885012206020)
C44  VDC_V: 25V  ValueDisplayed: 10µF  [0603S]  (hidden comment: GRM188R61E106KA73D)
C45  Cap_F: 10nF  VDC_V: 16V  [0603S]  (hidden comment: C0603C103K4RACTU)
C46  VDC_V: 25V  ValueDisplayed: 1000pF  [0603S]  (hidden comment: GRM1885C1E102JA01D)
D4  value Bright Green  [WL-SMCW_Green_0805]  (hidden comment: 150080VS75000)
D5  value Bright Green  [WL-SMCW_Green_0805]  (hidden comment: 150080VS75000)
D6  Yellow  [0805_A]
D7  value Bright Green  [WL-SMCW_Green_0805]  (hidden comment: 150080VS75000)
D8  value Red  [WL-SMCW_RED_0805]  (hidden comment: 150080SS75000)
J4  691101710002  [691101710002]  (value not drawn)
J5  61300311121  [WURTH_61300311121]  (value not drawn)
J7  61300211121  [WURTH_61300211121]  (value not drawn)
J9  PEC10DAAN  [SULLINS_PEC10DAAN]
J10  691101710002  [691101710002]  (value not drawn)
J11  691101710002  [691101710002]  (value not drawn)
P1.6  TP_H0.45P0.75  [TP_H045P075]  (value not drawn)  (no BOM)
P1.7  TP_H0.45P0.75  [TP_H045P075]  (value not drawn)  (no BOM)
P2.0  TP_H0.45P0.75  [TP_H045P075]  (value not drawn)  (no BOM)
P2.1  TP_H0.45P0.75  [TP_H045P075]  (value not drawn)  (no BOM)
P2.2  TP_H0.45P0.75  [TP_H045P075]  (value not drawn)  (no BOM)
P2.3  TP_H0.45P0.75  [TP_H045P075]  (value not drawn)  (no BOM)
P3.1  TP_H0.45P0.75  [TP_H045P075]  (value not drawn)  (no BOM)
P3.4  TP_H0.45P0.75  [TP_H045P075]  (value not drawn)  (no BOM)
P3.7  TP_H0.45P0.75  [TP_H045P075]  (value not drawn)  (no BOM)
R20  ValueDisplayed: 0  [0603L]  (hidden comment: ERJ-3GEY0R00V)
R21  value 0  [0603L]  (hidden comment: CRCW06030000Z0EA)
R22  value 0  [0603L]  (hidden comment: CRCW06030000Z0EA)
R23  ValueDisplayed: 0.2  [2512]  (hidden comment: CRM2512-FX-R200ELF)
R24  ValueDisplayed: 0.2  [2512]  (hidden comment: CRM2512-FX-R200ELF)
R25  ValueDisplayed: 47k  [0603S]  (hidden comment: RC0603JR-0747KL)
R26  value 330  [0603L]  (hidden comment: CRCW0603330RJNEA)
R27  ValueDisplayed: 1.02k  [0603L]  (hidden comment: CRCW06031K02FKEA)
R28  ValueDisplayed: 1.02k  [0603L]  (hidden comment: CRCW06031K02FKEA)
R29  value 330  [0603L]  (hidden comment: CRCW0603330RJNEA)
R30  ValueDisplayed: 9.09k  [0603L]  (hidden comment: RT0603DRE079K09L)
R31  ValueDisplayed: 9.09k  [0603L]  (hidden comment: RT0603DRE079K09L)
R32  value 330  [0603L]  (hidden comment: CRCW0603330RJNEA)
R33  value 4.99k  [0603L]  (hidden comment: CRCW06034K99FKEA)
R34  ValueDisplayed: 10k  [0603L]  (hidden comment: CRCW060310K0JNEA)
R35  value 330  [0603L]  (hidden comment: CRCW0603330RJNEA)
R36  value 47k  [0603L]  (hidden comment: CRCW060347K0JNEA)
S1  430481025816  [430481025816]
SH-J7  60900213421  [Wurth_60900213421]  (value not drawn)
SH-J8  60900213421  [Wurth_60900213421]  (value not drawn)
SH-J9  60900213421  [Wurth_60900213421]  (value not drawn)
SH-J10  60900213421  [Wurth_60900213421]  (value not drawn)
SH-J11  60900213421  [Wurth_60900213421]  (value not drawn)
SH-J12  60900213421  [Wurth_60900213421]  (value not drawn)
SH-J13  60900213421  [Wurth_60900213421]  (value not drawn)
SH-J14  60900213421  [Wurth_60900213421]  (value not drawn)
SH-J15  60900213421  [Wurth_60900213421]  (value not drawn)
SH-J16  60900213421  [Wurth_60900213421]  (value not drawn)
SH-J17  60900213421  [Wurth_60900213421]  (value not drawn)
SH-J18  60900213421  [Wurth_60900213421]  (value not drawn)
SH-J19  60900213421  [Wurth_60900213421]  (value not drawn)
SH-J20  60900213421  [Wurth_60900213421]  (value not drawn)
TP1  5016  [Testpoint_Keystone_Compact]  (value not drawn)
TP7  CMP-0075110-1  [Harwin_D3082-05]  (value not drawn)
TP8  CMP-0075110-1  [Harwin_D3082-05]  (value not drawn)
TP13  5016  [Testpoint_Keystone_Compact]  (value not drawn)
TP14  5016  [Testpoint_Keystone_Compact]  (value not drawn)
TP15  5016  [Testpoint_Keystone_Compact]  (value not drawn)
TP16  5016  [Testpoint_Keystone_Compact]  (value not drawn)
TP17  5002  [Keystone5002]  (value not drawn)
TP18  5002  [Keystone5002]  (value not drawn)
TP19  5002  [Keystone5002]  (value not drawn)
TP20  5002  [Keystone5002]  (value not drawn)
TP21  5002  [Keystone5002]  (value not drawn)
TP22  5002  [Keystone5002]  (value not drawn)
TP23  5002  [Keystone5002]  (value not drawn)
TP24  5002  [Keystone5002]  (value not drawn)
TP25  5002  [Keystone5002]  (value not drawn)
TP26  5002  [Keystone5002]  (value not drawn)
U4  TPS70933DBVR  [DBV0005A_N]
U5  MSP430G2553IPW28R  [PW0028A_N]
U6  DRV8410PWPR  [PWP0016C-MFG]
U7  TLV6001IDCKR  [DCK0005A_N]
U8  TLV6001IDCKR  [DCK0005A_N]

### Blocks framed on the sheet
Power Connector / LDO: C26 C29-C32 J4 R20 TP1 TP7 TP8 U4
DRV8410/11: C33-C41 C44 C45 J7 J10 J11 R23 R24 SH-J7-SH-J9 TP13-TP16 U6
Low-Side CSA: C42 C43 R27 R28 R30 R31 U7 U8
MSP430G2553: C27 C28 C46 J5 P1.6 P1.7 P2.0-P2.3 P3.1 P3.4 P3.7 R21 R22 R25 R36 S1 SH-J10 U5
Signal Header: J9 SH-J11-SH-J20 TP17-TP26
LED Indicators/Miscellaneous: D4-D8 R26 R29 R32-R35

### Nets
GND: C26.2 C27.2 C28.2 C29.2(-) C30.2 C31.2 C32.2 C33.2 C34.2 C35.2 C37.2 C39.2 C40.2 C41.2 C42.2 C43.2 C44.2 C46.2 J4.2 J9.19 J9.20 R22.1 R23.1 R24.1 R26.1 R27.1 R28.1 R29.1 R32.1 R33.1 S1.3 S1.4 TP7.1 TP7.2 TP8.1 TP8.2 TP26.1 U4.2(GND) U5.28(DVSS) U6.13(GND) U6.17(Thermal_Pad) U7.2(V-) U8.2(V-)
VCC: C27.1 C28.1 C32.1 C42.1 C43.1 D8.2(A) J9.17 J9.18 R21.2 R25.2 R34.2 R36.2 TP25.1 U4.5(OUT) U5.1(DVCC) U7.5(V+) U8.5(V+)
VM: C29.1(+) C30.1 C31.1 C33.1 C45.2 D7.2(A) J4.1 R20.2 TP1.1 U6.12(VM)
AIN1: J9.2 TP17.1 U6.16(AIN1)
AIN1_MCU: J9.1 U5.20(P3.6/TA0.2)
AIN2: J9.4 TP18.1 U6.15(AIN2)
AIN2_MCU: J9.3 U5.19(P3.5/TA0.1)
AISEN: C34.1 J7.1 R23.2 U6.3(AISEN) U7.1(IN+)
AOUT1: C36.1 C40.1 J10.1 TP13.1 U6.2(AOUT1)
AOUT2: C36.2 C37.1 J10.2 TP14.1 U6.4(AOUT2)
BIN1: J9.6 TP19.1 U6.9(BIN1)
BIN1_MCU: J9.5 U5.14(P3.3/TA1.2)
BIN2: J9.8 TP20.1 U6.10(BIN2)
BIN2_MCU: J9.7 U5.13(P3.2/TA1.1)
BISEN: C35.1 J7.2 R24.2 U6.6(BISEN) U8.1(IN+)
BOUT1: C38.2 C39.1 J11.2 TP16.1 U6.7(BOUT1)
BOUT2: C38.1 C41.1 J11.1 TP15.1 U6.5(BOUT2)
DEV_ID: R21.1 R22.2 U5.5(P1.3/ADC10CLK/CAOUT/VREF-/VEREF-/A3/CA3)
GUI_STATUS: D5.2(A) U5.9(P3.0/TA0.2)
MCU_STATUS: D4.2(A) U5.2(P1.0/TA0CLK/ACLK/A0/CA0)
MCU_UARTRXD: U5.3(P1.1/TA0.0/UCA0RXD/UCA0SOMI/A1/CA1)
MCU_UARTTXD: U5.4(P1.2/TA0.1/UCA0TXD/UCA0SIMO/A2/CA2)
nFAULT: J9.10 R34.1 R35.1 TP21.1 U6.8(~{FAULT})
nFAULT_MCU: J9.9 U5.18(P2.5/TA1.2)
nSLEEP: J9.12 TP22.1 U6.1(~{SLEEP})
nSLEEP_MCU: J9.11 U5.17(P2.4/TA1.2)
PUSH: J5.3 R36.1 U5.27(XIN/P2.6/TA0.1)
RST/SBWTDIO: C46.1 J5.1 R25.1 U5.24(~{RST}/NMI/SBWTDIO)
STALL: D6.2(A) U5.26(XOUT/P2.7)
TST/SBWTCK: U5.25(TEST/SBWTCK)
VSENSE_A: J9.14 R30.2 TP23.1 U7.4(OUT)
VSENSE_A_MCU: J9.13 U5.7(P1.5/TA0.0/UCB0CLK/UCA0STE/A5/CA5/TMS)
VSENSE_B: J9.16 R31.2 TP24.1 U8.4(OUT)
VSENSE_B_MCU: J9.15 U5.6(P1.4/SMCLK/UCB0STE/UCA0CLK/VREF+/VEREF+/A4/CA4/TCK)
NetC26_1: C26.1 R20.1 U4.1(IN) U4.3(EN)
NetC44_1: C44.1 U6.14(NC)
NetC45_1: C45.1 U6.11(NC)
NetD4_1: D4.1(K) R26.2
NetD5_1: D5.1(K) R29.2
NetD6_1: D6.1(K) R32.2
NetD7_1: D7.1(K) R33.2
NetD8_1: D8.1(K) R35.2
NetJ5_2: J5.2 S1.1 S1.2
NetP1.6_1: P1.6.1 U5.22(P1.6/TA0.1/UCB0SOMI/UCB0SCL/A6/CA6/TDI/TCLK)
NetP1.7_1: P1.7.1 U5.23(P1.7/CAOUT/UCB0SIMO/UCB0SDA/A7/CA7/TDO/TDI)
NetP2.0_1: P2.0.1 U5.10(P2.0/TA1.0)
NetP2.1_1: P2.1.1 U5.11(P2.1/TA1.1)
NetP2.2_1: P2.2.1 U5.12(P2.2/TA1.1)
NetP2.3_1: P2.3.1 U5.16(P2.3/TA1.0)
NetP3.1_1: P3.1.1 U5.8(P3.1/TA1.0)
NetP3.4_1: P3.4.1 U5.15(P3.4/TA0.0)
NetP3.7_1: P3.7.1 U5.21(P3.7/TA1CLK/CAOUT)
NetR27_2: R27.2 R30.1 U7.3(IN-)
NetR28_2: R28.2 R31.1 U8.3(IN-)

Not connected (* = marked no-connect by the designer): U4 4(NC)*

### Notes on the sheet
- (near TP13) add jumper for parallel mode
- DNP for final ver
- (near J4) 16-A MAX
- (near J10) 16-A MAX
- (near J11) 16-A MAX
- Low-side CSA:
  Gain=10 V/V
  Rail-Rail, 1MHz GBW (100kHz -3dB)
  Input Offset = 0.75mV
- during parallel mode
- (near J7) Short J7 to parallel AISEN and BISEN
- I_trip=0.2V/R_SENSE
- Current limit (ITRIP):
  DRV8410:
  RSENSE=0.2 (2W 1%)
  - 1A
  - 2A (parallel)
  DRV8411:
  RSENSE=0.1 (3W 1%)
  - 2A
  - 4A (paralleled)
- DEV_ID=0 -> DRV8410EVM
- (near R21) DEV_ID=1 -> DRV8411EVM
- SELECT PUSH
- BUTTON FUNCT
- yellow LED
- Default: shunts placed on J9
- Remove shunts to control motor driver with external MCU
- Or to use the on-board MCU to control external motor driver

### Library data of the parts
C26 = CMP-0006833-4: CAP, CERM, 1 uF, 25 V, +/- 10%, X7R, 0603; Manufacturer: Wurth Elektronik; TaMin_C: -55°C; Polarized: N; SizeAreaWB_mm2: 4.68; Value1: Unknown; U/M: EA; Value: 1uF; TaMax_C: 125°C; SizeZ_mm: 1; SizeX_mm: 1.6; SizeY_mm: 0.8; Cap_Case: 0603; SizeArea_mm2: 1.28; AEC Category: Q200
C27 = CMP-0007690-2: CAP, CERM, 4.7 uF, 10 V, +/- 10%, X7R, 0805; Manufacturer: Wurth Elektronik; TaMin_C: -55°C; Polarized: N; SizeAreaWB_mm2: 6.75; Value1: Unknown; U/M: EA; Value: 4.7uF; TaMax_C: 125°C; SizeZ_mm: 1.45; SizeX_mm: 2; SizeY_mm: 1.25; Cap_Case: 0805; SizeArea_mm2: 2.5; AEC Category: Q200
C28 C42 C43 = CMP-0064931-4: as C7 on sheet ezFET
C29 = CMP-0011161-2: CAP, AL, 47 uF, 50 V, +/- 20%, SMD; Manufacturer: Wurth Elektronik; TaMin_C: -55°C; Polarized: Y; SizeAreaWB_mm2: 79.98; Value1: Unknown; U/M: EA; Value: 47uF; TaMax_C: 105°C; SizeZ_mm: 7.7; SizeX_mm: 7.3; SizeY_mm: 6.6; Cap_Case: 6.3x7.7mm; SizeArea_mm2: 48.18; CompType: Capacitor; AEC Qualified: N; Cap_F: 47µF; IRMS_A: 230mA; AEC Category: Q200
C30 = CMP-0007696-2: CAP, CERM, 1 uF, 50 V, +/- 10%, X7R, 0805; Manufacturer: Wurth Elektronik; TaMin_C: -55°C; Polarized: N; SizeAreaWB_mm2: 6.75; Value1: Unknown; U/M: EA; Value: 1uF; TaMax_C: 125°C; SizeZ_mm: 1.45; SizeX_mm: 2; SizeY_mm: 1.25; Cap_Case: 0805; SizeArea_mm2: 2.5; AEC Category: Q200
C31 C33 = CMP-0006837-4: CAP, CERM, 0.1 uF, 50 V, +/- 10%, X7R, 0603; Manufacturer: Wurth Elektronik; Polarized: N; Value: 0.1uF; U/M: EA; Cap_F: 100nF; Value1: Unknown; VDC_V: 50V; TaMin_C: -55°C; TaMax_C: 125°C; Cap_Case: 0603; SizeArea_mm2: 1.28; SizeAreaWB_mm2: 4.68; SizeX_mm: 1.6; SizeY_mm: 0.8; SizeZ_mm: 1; AEC Category: Q200
C32 = CMP-0007330-5: CAP, CERM, 4.7 uF, 10 V, +/- 20%, X5R, 0603; Manufacturer: MuRata; TaMin_C: -55°C; Polarized: N; SizeAreaWB_mm2: 4.68; Value1: Unknown; U/M: EA; Value: 4.7uF; TaMax_C: 85°C; SizeZ_mm: 1; SizeX_mm: 1.6; SizeY_mm: 0.8; Cap_Case: 0603; SizeArea_mm2: 1.28; Cap_F: 4.7µF; AEC Category: Q200
C34 C35 = CMP-0006826-4: CAP, CERM, 1000 pF, 16 V, +/- 10%, X7R, 0603; Manufacturer: Wurth Elektronik; TaMin_C: -55°C; Polarized: N; SizeAreaWB_mm2: 4.68; Value1: Unknown; U/M: EA; Value: 1000pF; TaMax_C: 125°C; SizeZ_mm: 1; SizeX_mm: 1.6; SizeY_mm: 0.8; Cap_Case: 0603; SizeArea_mm2: 1.28; AEC Category: Q200
C36-C41 = CMP-0064933-4: CAP, CERM, 1000 pF, 50 V,+/- 10%, X7R, 0603; Manufacturer: Wurth Elektronik; TaMin_C: -55°C; Polarized: N; SizeAreaWB_mm2: 4.68; Value1: Unknown; U/M: EA; Value: 1000pF; TaMax_C: 125°C; SizeZ_mm: 1; SizeX_mm: 1.6; SizeY_mm: 0.8; Cap_Case: 0603; SizeArea_mm2: 1.28; AEC Category: Q200
C44 = CMP-0860569-1: CAP, CERM, 10 µF, 25 V,+/- 10%, X5R, 0603; Manufacturer: MuRata; SizeZ_mm: 1; AEC Category: Q200; AEC Qualified: N; TaMin_C: -55°C; Cap_Case: 0603; SizeY_mm: 0.8; SizeAreaWB_mm2: 4.68; SizeArea_mm2: 1.28; TaMax_C: 85°C; SizeX_mm: 1.6; Value: 10uF; U/M: EA
C45 = CMP-0006853-4: CAP, CERM, 0.01 uF, 16 V, +/- 10%, X7R, 0603; Manufacturer: Kemet; TaMin_C: -55°C; Polarized: N; SizeAreaWB_mm2: 4.68; Value1: Unknown; U/M: EA; Value: 0.01uF; TaMax_C: 125°C; SizeZ_mm: 1; SizeX_mm: 1.6; SizeY_mm: 0.8; Cap_Case: 0603; SizeArea_mm2: 1.28; AEC Category: Q200
C46 = CMP-0007159-1: CAP, CERM, 1000 pF, 25 V, +/- 5%, C0G/NP0, 0603; Manufacturer: MuRata; Alternate Manufacturer: Wurth Elektronik; Alternate PartNumber: 885012206059; TaMin_C: -55°C; Polarized: N; SizeAreaWB_mm2: 4.68; Value1: Unknown; U/M: EA; Value: 1000pF; TaMax_C: 125°C; SizeZ_mm: 1; SizeX_mm: 1.6; SizeY_mm: 0.8; Cap_Case: 0603; SizeArea_mm2: 1.28; Cap_F: 1nF; AEC Category: Q200
D4 D5 D7 = CMP-0002960-2: LED, Bright Green, SMD; Manufacturer: Wurth Elektronik; Io_A: 20mA; Power_TotalModule: 72mW; Vr_V: 5V; Tjmax_C: 85°C; Value1: 0.072W; U/M: EA; Angle: 140; Vf_V: 2V; Type: AlInGaP
D6 = CMP-1426-00012-1: SMD mono-color Chip LED, WL-SMCW, Yellow; Manufacturer: Wuerth Elektronik; PartNumber: 150080YS75000
D8 = CMP-0002951-3: LED, Red, SMD; Manufacturer: Wurth Elektronik; Type: AlInGaP; Angle: 140; Vr_V: 5V; Ir_A: 25µA; Vf_V: 1.9V; Value1: 0.072W; Tjmax_C: 85°C; Io_A: 30mA; Power_TotalModule: 72mW
J4 J10 J11 = CMP-1502-03256-1: Series 101 - 5.00 mm Horizontal Entry Modular with Pressure Clamp WR-TBL, 2 pin; Manufacturer: Wurth Elektronik; Pin Number: 2; Pitch: 5.00mm
J5 = CMP-0054796-2: Header, 2.54 mm, 3x1, Gold, TH; Manufacturer: Wurth Elektronik; Pitch_mm: 2.54; Green_Lifecycle: Active; Cert_UL: Y; Shrouded: N; Green_REACh: Passed; Gender: Male; Row_Count: 1
J7 = CMP-0054794-2: Header, 2.54 mm, 2x1, Gold, TH; Manufacturer: Wurth Elektronik; Shrouded: N; Gender: Male; Green_REACh: Passed; Pitch_mm: 2.54; Green_Lifecycle: Active; Row_Count: 1; Cert_UL: Y
J9 = CMP-0054623-2: Header, 2.54mm, 10x2, Tin, TH; Manufacturer: Sullins Connector Solutions; Current_A: 3A; Green_Lifecycle: Not Set; Shrouded: N; Gender: Male; Green_REACh: Incomplete; Row_Count: 2; RowSpacing_mm: 2.54; Cert_UL: Y
P1.6 P1.7 P2.0-P2.3 P3.1 P3.4 P3.7 = CMP-0003719-1: Testpoint; Manufacturer: Texas Instruments; CompType: Pad
R20 = CMP-0025874-3: RES, 0, 5%, 0.1 W, 0603; Manufacturer: Panasonic; Value: 0; Value_Code: 0000; Power_W: 100mW; Value2: 0.1W; VDC_V: 50V; TempCo: 600 ppm/C; EIA_Code: E24; U/M: EA; SizeArea_mm2: 1.28; SizeX_mm: 1.6; SizeY_mm: 0.8; SizeZ_mm: 1; AEC Category: Q200
R21 R22 = CMP-0025697-4: RES, 0, 5%, 0.1 W, AEC-Q200 Grade 0, 0603; Manufacturer: Vishay-Dale; Value_Code: 0000; Power_W: 100mW; Value2: 0.1W; VDC_V: 75V; TempCo: 200 ppm/C; EIA_Code: E24; AEC Category: Q200; AEC Qualified: Y; SizeArea_mm2: 1.28; SizeX_mm: 1.6; SizeY_mm: 0.8; SizeZ_mm: 1
R23 R24 = CMP-0015754-2: RES, 0.2, 1%, 2 W, 2512; Manufacturer: Bourns; Power_W: 2W; TempCo: 100 ppm/C; Value_Code: R200; U/M: EA; Value: 0.2; EIA_Code: E96; SizeX_mm: 6.3; SizeY_mm: 3.2; SizeZ_mm: 0.71; SizeArea_mm2: 20.16; AEC Qualified: N; AEC Category: Q200
R25 = CMP-0025925-5: RES, 47 k, 5%, 0.1 W, 0603; Manufacturer: Yageo; Power_W: 100mW; TempCo: 100 ppm/C; Value_Code: 47k0; Value: 47k; EIA_Code: E24; SizeX_mm: 1.6; SizeY_mm: 0.8; SizeZ_mm: 1; Value2: 0.1W; SizeArea_mm2: 1.28; AEC Qualified: N; VDC_V: 75V; AEC Category: Q200; SizeAreaWB_mm2: 4.68
R26 R29 R32 R35 = CMP-0025785-4: RES, 330, 5%, 0.1 W, AEC-Q200 Grade 0, 0603; Manufacturer: Vishay-Dale; Value_Code: 330R; Power_W: 100mW; Value2: 0.1W; VDC_V: 75V; TempCo: 200 ppm/C; EIA_Code: E24; AEC Category: Q200; AEC Grade: 0; AEC Qualified: Y; SizeArea_mm2: 1.28; SizeX_mm: 1.6; SizeY_mm: 0.8; SizeZ_mm: 1
R27 R28 = CMP-0022110-4: RES, 1.02 k, 1%, 0.1 W, AEC-Q200 Grade 0, 0603; Manufacturer: Vishay-Dale; Power_W: 100mW; TempCo: 100 ppm/C; Value_Code: 1k02; Value: 1.02k; EIA_Code: E96; SizeX_mm: 1.6; SizeY_mm: 0.8; SizeZ_mm: 1; Value2: 0.1W; SizeArea_mm2: 1.28; AEC Qualified: Y; VDC_V: 75V; AEC Category: Q200; AEC Grade: 0
R30 R31 = CMP-0025668-3: RES, 9.09 k, 0.5%, 0.1 W, 0603; Manufacturer: Yageo America; Power_W: 100mW; TempCo: 50 ppm/C; Value_Code: 9k09; U/M: EA; Value: 9.09k; EIA_Code: E192; SizeX_mm: 1.6; SizeY_mm: 0.8; SizeZ_mm: 1; Value2: 0.1W; SizeArea_mm2: 1.28; VDC_V: 75V; AEC Category: Q200
R33 = CMP-0022458-4: RES, 4.99 k, 1%, 0.1 W, AEC-Q200 Grade 0, 0603; Manufacturer: Vishay-Dale; Value_Code: 4k99; Power_W: 100mW; Value2: 0.1W; VDC_V: 75V; TempCo: 100 ppm/C; EIA_Code: E96; AEC Category: Q200; AEC Qualified: Y; AEC Grade: 0; SizeArea_mm2: 1.28; SizeX_mm: 1.6; SizeY_mm: 0.8; SizeZ_mm: 1
R34 = CMP-0025701-4: RES, 10 k, 5%, 0.1 W, AEC-Q200 Grade 0, 0603; Manufacturer: Vishay-Dale; Value: 10k; Value_Code: 10k0; Power_W: 100mW; Value2: 0.1W; VDC_V: 75V; TempCo: 200 ppm/C; EIA_Code: E24; AEC Category: Q200; AEC Qualified: Y; AEC Grade: 0; SizeArea_mm2: 1.28; SizeX_mm: 1.6; SizeY_mm: 0.8; SizeZ_mm: 1
R36 = CMP-0025814-4: RES, 47 k, 5%, 0.1 W, AEC-Q200 Grade 0, 0603; Manufacturer: Vishay-Dale; Value_Code: 47k0; Power_W: 100mW; Value2: 0.1W; VDC_V: 75V; TempCo: 200 ppm/C; EIA_Code: E24; AEC Category: Q200; AEC Qualified: Y; AEC Grade: 0; SizeArea_mm2: 1.28; SizeX_mm: 1.6; SizeY_mm: 0.8; SizeZ_mm: 1
S1 = CMP-1452-00025-1: WS-TASV SMD Tact Switch 6X6 mm; Manufacturer: Wuerth Elektronik; NoPins: 04
SH-J7-SH-J20 = CMP-0003761-2: as SH-J1 on sheet ezFET
TP1 TP13-TP16 = CMP-0055153-1: Test Point, Compact, SMT; Manufacturer: Keystone; CNHeader: FALSE; Green_Lifecycle: Active; Green_REACh: Passed; CT: TRUE
TP7 TP8 = CMP-0075110-1: 1mm Uninsulated Shorting Plug, 10.16mm spacing, TH; PartNumber: D3082-05; Manufacturer: Harwin; CompType: Jumper Wire; CNHeader: False; Green_Lifecycle: Active; Green_REACh: Passed
TP17-TP26 = CMP-0055139-2: Test Point, Miniature, White, TH; Manufacturer: Keystone Electronics; ContactFinish: Silver; Green_REACh: Passed; CT: TRUE; Green_Lifecycle: Active; CNHeader: FALSE
U4 = CMP-0073793-1: 150-mA, 30-V, Ultra-Low IQ, Wide Input Low-Dropout Regulator with Reverse Current Protection, DBV0005A (SOT-23-5); Alternate PartNumber: TPS70933DBVT; Alternate Manufacturer: Texas Instruments; Green_Lifecycle: Active; SizeAreaWB_mm2: 14.82; Green_REACh: Passed; U/M: EA; SizeZ_mm: 1.45; SizeX_mm: 2.8; SizeY_mm: 2.9; SizeArea_mm2: 8.12; CompType: IC
U5 = CMP-0039449-2: MSP430G2x53, MSP430G2x13 Mixed Signal Microcontroller, PW0028A (TSSOP-28); Manufacturer: Texas Instruments; Temp Sensor: Yes; ADC: 10-bit SAR; SubFamily: Value Line; Timers - 16-bit: 2; ADC Channels: 8; SRAM(B): 512; Frequency(MHz): 16; GPIO: 24; USCI_B (I2C & SPI): 1; Eco-Plan: Green (RoHS & no Sb/Br); AEC Category: Q200; AEC Qualified: N; CompType: IC; SizeAreaWB_mm2: 98.28; SizeArea_mm2: 62.08; SizeX_mm: 6.4; SizeY_mm: 9.7; SizeZ_mm: 1.2
U6 = CMP-0094668-1: Dual H-Bridge Motor Driver with Current Regulation; Manufacturer: Texas Instruments; SizeZ_mm: 1.2mm; TaMin_C: -40°C; Switching Frequency: 100kHz; TJmax_C: +150°C; Max Supply Voltage: 11V; TaMax_C: +125°C; AEC Qualified: No; Number Of Outputs: 4; Min Supply Voltage: 1.65V; Standoff Height: 0.05mm
U7 U8 = CMP-0073548-2: 1-MHz, Low-Power Operational Amplifier for Cost-Sensitive Systems, DCK0005A (SOT-SC70-5); Alternate PartNumber: TLV6001IDCKT; Alternate Manufacturer: Texas Instruments; SizeAreaWB_mm2: 9.3; SizeZ_mm: 1.1; SizeX_mm: 2.1; SizeY_mm: 2.0; SizeArea_mm2: 4.2; CompType: IC; AEC Category: Q200; AEC Qualified: N

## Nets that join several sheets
GND: ezFET (46 pins), MD062E2_Sch (43 pins)
VCC: ezFET (J3.10), MD062E2_Sch (17 pins)
MCU_UARTRXD: ezFET (J3.8), MD062E2_Sch (U5.3)
MCU_UARTTXD: ezFET (J3.6), MD062E2_Sch (U5.4)
RST/SBWTDIO: ezFET (J3.4), MD062E2_Sch (C46.1 J5.1 R25.1 U5.24)
TST/SBWTCK: ezFET (J3.2), MD062E2_Sch (U5.25)

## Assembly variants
001: not fitted C34 C35 C36 C37 C38 C39 C40 C41 C44 C45 FID1 FID2 FID3 R12 R18 R21 U3; alternate parts U6 -> CMP-0094668-1
002: not fitted C34 C35 C36 C37 C38 C39 C40 C41 C44 C45 R12 R18 R22 U3; alternate parts U6 -> CMP-0094670-3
